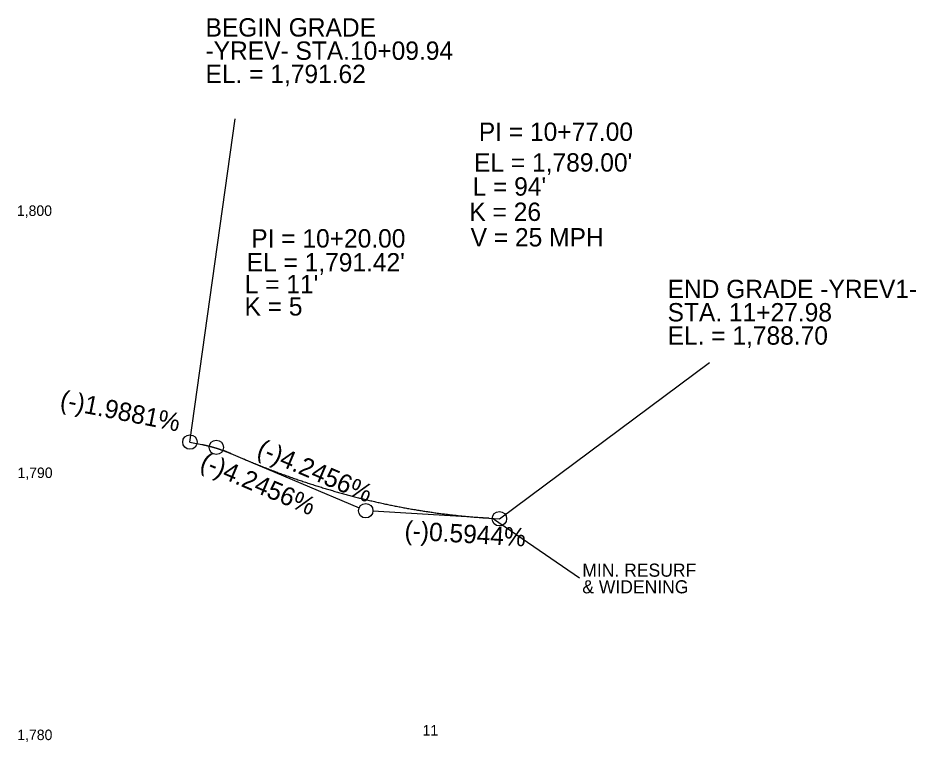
# Model space of a CAD drawing. Extents: x 579695 to 581182, y -53686 to -53165.
# Drawn here: x 580839.5 to 581182.1, y -53441.7 to -53165.4 of the extents above; entities that cross this region are included whole.
import ezdxf

# ---------------------------------------------------------------- set-up
doc = ezdxf.new("R2010")
doc.units = 0
for name, color, linetype in [('Default', 7, 'Continuous'), ('Prop Vertical Profile Grade', 7, 'Continuous'), ('Prop Vertical Profile Grade Label', 7, 'Continuous'), ('Prop VPI Label', 7, 'Continuous')]:
    doc.layers.add(name, color=color, linetype=linetype)

msp = doc.modelspace()

# ---------------------------------------------------------------- linework, layer by layer
at = {"layer": 'Prop Vertical Profile Grade'}
for p, q in [((580905.14, -53327.26), (580909.68, -53328.16)), ((580920.72, -53331.6), (580925.2, -53333.51)), ((581019.2, -53356.25), (581023.18, -53356.49))]:
    msp.add_line(p, q, dxfattribs=at)
for points in [[(580909.68, -53328.16), (580909.91, -53328.21), (580910.13, -53328.25), (580910.35, -53328.3), (580910.57, -53328.35), (580910.79, -53328.39), (580911.01, -53328.44), (580911.23, -53328.49), (580911.45, -53328.55), (580911.67, -53328.6), (580911.89, -53328.65), (580912.11, -53328.71), (580912.33, -53328.76), (580912.55, -53328.82), (580912.78, -53328.87), (580913, -53328.93), (580913.22, -53328.99), (580913.44, -53329.05), (580913.66, -53329.11), (580913.88, -53329.18), (580914.1, -53329.24), (580914.32, -53329.3), (580914.54, -53329.37), (580914.76, -53329.44), (580914.98, -53329.5), (580915.2, -53329.57), (580915.42, -53329.64), (580915.65, -53329.71), (580915.87, -53329.78), (580916.09, -53329.85), (580916.31, -53329.93), (580916.53, -53330), (580916.75, -53330.08), (580916.97, -53330.15), (580917.19, -53330.23), (580917.41, -53330.31), (580917.63, -53330.39), (580917.85, -53330.47), (580918.07, -53330.55), (580918.29, -53330.63), (580918.52, -53330.72), (580918.74, -53330.8), (580918.96, -53330.89), (580919.18, -53330.97), (580919.4, -53331.06), (580919.62, -53331.15), (580919.84, -53331.24), (580920.06, -53331.33), (580920.28, -53331.42), (580920.5, -53331.51), (580920.72, -53331.6)], [(580925.2, -53333.51), (580927.08, -53334.3), (580928.96, -53335.07), (580930.84, -53335.84), (580932.72, -53336.59), (580934.6, -53337.32), (580936.48, -53338.05), (580938.36, -53338.76), (580940.24, -53339.45), (580942.12, -53340.13), (580944, -53340.8), (580945.88, -53341.45), (580947.76, -53342.1), (580949.64, -53342.72), (580951.52, -53343.33), (580953.4, -53343.93), (580955.28, -53344.52), (580957.16, -53345.09), (580959.04, -53345.65), (580960.92, -53346.19), (580962.8, -53346.72), (580964.68, -53347.24), (580966.56, -53347.74), (580968.44, -53348.23), (580970.32, -53348.71), (580972.2, -53349.17), (580974.08, -53349.62), (580975.96, -53350.05), (580977.84, -53350.47), (580979.72, -53350.88), (580981.6, -53351.27), (580983.48, -53351.65), (580985.36, -53352.02), (580987.24, -53352.37), (580989.12, -53352.71), (580991, -53353.03), (580992.88, -53353.34), (580994.76, -53353.64), (580996.64, -53353.92), (580998.52, -53354.19), (581000.4, -53354.45), (581002.28, -53354.69), (581004.16, -53354.92), (581006.04, -53355.13), (581007.92, -53355.34), (581009.8, -53355.52), (581011.68, -53355.7), (581013.56, -53355.86), (581015.44, -53356), (581017.32, -53356.13), (581019.2, -53356.25)]]:
    msp.add_spline(points, degree=3, dxfattribs=at)
at = {"layer": 'Prop VPI Label'}
for p, q in [((580905.14, -53327.26), (580922.38, -53203.89)), ((581023.18, -53356.49), (581103.37, -53296.91)), ((580909.68, -53328.16), (580912.51, -53328.72)), ((580920.72, -53331.6), (580917.74, -53330.33)), ((580925.2, -53333.51), (580969.67, -53352.39)), ((581019.2, -53356.25), (580974.95, -53353.62)), ((581020.89, -53356.51), (581053.71, -53379.11))]:
    msp.add_line(p, q, dxfattribs=at)
for centre in [(580905.14, -53327.26), (580915.2, -53329.26), (580972.2, -53353.46), (581023.18, -53356.49)]:
    msp.add_circle(centre, 2.75, dxfattribs=at)

# ---------------------------------------------------------------- texts
at = {"layer": 'Default'}
for s, p in [('1,800', (580839.13, -53240.96)), ('1,790', (580839.35, -53340.96)), ('1,780', (580839.28, -53440.96)), ('11', (580993.88, -53439.21))]:
    msp.add_text(s, height=4, dxfattribs=at).set_placement(p)
at = {"layer": 'Prop Vertical Profile Grade Label'}
for s, rotation, p in [('(-)1.9881%', 348.7558, (580855.21, -53314.27)), ('(-)4.2456%', 336.9958, (580930.22, -53332.37)), ('(-)4.2456%', 336.9958, (580908.5, -53337.28)), ('(-)0.5944%', 356.5986, (580986.84, -53364.35))]:
    msp.add_text(s, height=7, rotation=rotation, dxfattribs=at).set_placement(p)
at = {"layer": 'Prop VPI Label'}
for s, height, p in [('BEGIN GRADE', 7, (580911.07, -53172.54)), ('-YREV- STA.10+09.94', 7, (580911.07, -53181.41)), ('EL. = 1,791.62', 7, (580911.07, -53190.28)), ('PI = 10+77.00', 7, (581015.33, -53212.33)), ("EL = 1,789.00'", 7, (581013.51, -53224.06)), ("L = 94'", 7, (581012.94, -53233.23)), ('K = 26', 7, (581011.74, -53242.88)), ('PI = 10+20.00', 7, (580928.52, -53253.02)), ('V = 25 MPH', 7, (581012.21, -53252.61)), ("EL = 1,791.42'", 7, (580926.77, -53262.15)), ("L = 11'", 7, (580926.03, -53270.48)), ('END GRADE -YREV1- ', 7, (581087.34, -53272.34)), ('K = 5', 7, (580925.95, -53278.98)), ('STA. 11+27.98', 7, (581087.34, -53281.22)), ('EL. = 1,788.70', 7, (581087.34, -53290.09)), ('MIN. RESURF', 5, (581054.8, -53378.63)), ('& WIDENING', 5, (581054.8, -53384.97))]:
    msp.add_text(s, height=height, dxfattribs=at).set_placement(p)

doc.saveas('drawing.dxf')
